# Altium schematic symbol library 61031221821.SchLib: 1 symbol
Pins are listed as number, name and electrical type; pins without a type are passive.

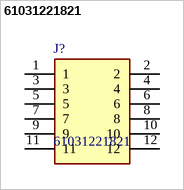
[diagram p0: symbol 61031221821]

## 61031221821
designator J?
Headers & Wire Housings WR-PHD 2.54 mm Dual SMT Socket Header T&R; Manufacturer_Name: Wurth Elektronik; Geometry.Height: 7.75mm
footprint 61031221821
pins: 1, 2, 3, 4, 5, 6, 7, 8, 9, 10, 11, 12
